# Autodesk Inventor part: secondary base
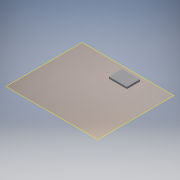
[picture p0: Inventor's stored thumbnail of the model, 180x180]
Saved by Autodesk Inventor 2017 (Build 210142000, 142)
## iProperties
Created: 2017-05
Part Number: secondary base
Material: Generic
Document SubType Name: Modeling
Designer: 1717440
Density: 1 g/cm^3
Appearance: Default
Author: 1717440
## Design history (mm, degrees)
workplane "Work Plane1"
sketch "Sketch1"
  geometry: L1 (-0.22, 54)-(27, 54) reference; L2 (18.815, 54)-(1.815, 54) reference; L3 (1.815, 54)-(1.815, 32.156) reference; L4 (1.815, 32.156)-(18.815, 32.156) reference; L5 (18.815, 32.156)-(18.815, 54) reference; L6 (-2, 54)-(28, 54); L7 (28, 54)-(28, 31.8); L8 (28, 31.8)-(-2, 31.8); L9 (-2, 31.8)-(-2, 54); 1 further point
  constraints: 8 end point, 2 parallel, 1 collinear, 1 horizontal, 1 perpendicular
  dimensions: "d0" = 21.844 distance of L4.end L2.start (derived); "d1" = 22.2 distance of L6.end L7.end
extrude "Extrusion1" new body sketch "Sketch1" distance "d2" = 4; taper "d3" = 0 deg
sketch "Sketch2"
  geometry: L1 (30, -4)-(0, -4) reference; L2 (30, 0)-(30, -4) reference; C1 r 1 at (26.43, -2.237) reference; C2 r 1 at (4.495, -2.237) reference; C3 r 0.95 at (25.968, -2.237); C4 r 0.95 at (4.033, -2.237); 1 further point
  constraints: 2 centre point
  dimensions: "d4" = 21.93488 distance of C2.centre C1.centre (derived); "d5" = 2 diameter of C1 (derived); "d6" = 1.9 diameter of C3; "d7" = 1.9 diameter of C4; "d8" = 21.935 distance of C4.centre C3.centre; "d9" = 1.76318 distance from line of L1 C1.centre (derived); "d10" = 1.76318 distance from line of L1 C3.centre; "d11" = 4.0325 distance from line of L2 C3.centre (derived)
extrude "Extrusion2" join sketch "Sketch2" distance "d13" = 2; taper "d14" = 0 deg
sketch "Sketch3"
  geometry: L1 (2, 54)-(-28, 54) reference; L2 (-28, 54)-(-28, 31.8) reference; L3 (-28, 31.8)-(2, 31.8) reference; L4 (2, 31.8)-(2, 54) reference; L5 (-2.2, 36)-(-23.8, 36); L6 (-23.8, 36)-(-23.8, 49.8); L7 (-23.8, 49.8)-(-2.2, 49.8); L8 (-2.2, 49.8)-(-2.2, 36); C1 r 1.538 at (-2.2, 36); C2 r 1.538 at (-2.2, 49.8); C3 r 1.538 at (-23.8, 36); C4 r 1.538 at (-23.8, 49.8); 1 further point
  constraints: 8 end point, 4 centre point, 4 coincident, 3 other
  dimensions: "d16" = 3.075 diameter of C1; "d17" = 3.075 diameter of C2; "d18" = 3.075 diameter of C3; "d19" = 3.075 diameter of C4
extrude "Extrusion3" join sketch "Sketch3" distance "d20" = 4; taper "d21" = 0 deg
body "Solid1"
node "Reference1"
node "Reference2"
node "Reference3"
node "Reference4"
